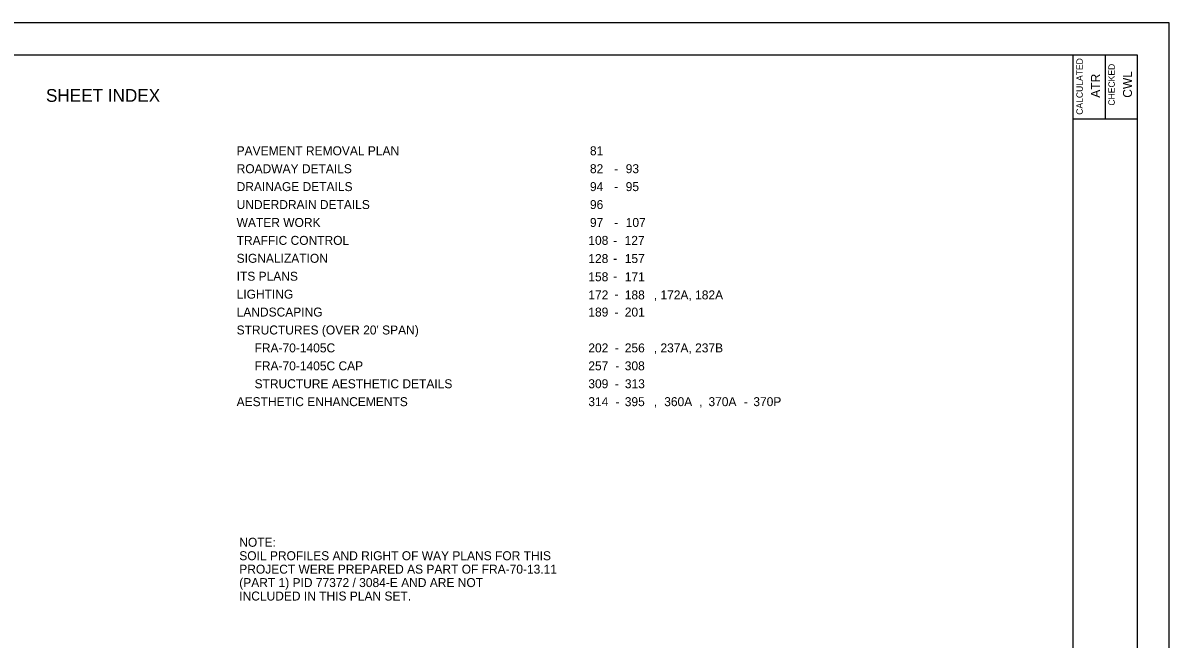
# Model space of a CAD drawing. Extents: x -42.2 to 34, y 0 to 22.
# Drawn here: x 16.1 to 34, y 12.37 to 22 of the extents above; entities that cross this region are included whole.
import ezdxf

# ---------------------------------------------------------------- set-up
doc = ezdxf.new("R2010")
doc.units = 0
for name, color, linetype in [('SH_Border', 7, 'Continuous'), ('SH_Cut_Line', 7, 'Continuous'), ('SH_Data', 7, 'Continuous')]:
    doc.layers.add(name, color=color, linetype=linetype)

msp = doc.modelspace()

# ---------------------------------------------------------------- linework, layer by layer
at = {"layer": 'SH_Border'}
for p, q in [((32.5, 0.5), (32.5, 21.5)), ((33, 21.5), (33, 20.5)), ((32.5, 20.5), (33.5, 20.5))]:
    msp.add_line(p, q, dxfattribs=at)
msp.add_lwpolyline([(2, 21.5), (33.5, 21.5), (33.5, 0.5), (2, 0.5)], close=True, dxfattribs=at)
at = {"layer": 'SH_Cut_Line'}
msp.add_lwpolyline([(0, 0), (34, 0), (34, 22), (0, 22)], close=True, dxfattribs=at)

# ---------------------------------------------------------------- texts
at = {"layer": 'SH_Data'}
for s, height, p in [('CALCULATED', 0.1, (32.652, 20.565)), ('CHECKED', 0.1, (33.152, 20.708)), ('ATR ', 0.14, (32.92, 20.831)), ('CWL ', 0.14, (33.42, 20.831))]:
    msp.add_text(s, height=height, rotation=90, dxfattribs=at).set_placement(p)
for s, height, p in [('SHEET INDEX ', 0.2, (16.459, 20.767)), ('PAVEMENT REMOVAL PLAN', 0.14, (19.437, 19.932)), ('81', 0.14, (24.955, 19.932)), ('ROADWAY DETAILS', 0.14, (19.437, 19.652)), ('82', 0.14, (24.955, 19.652)), ('-', 0.14, (25.333, 19.652)), ('93', 0.14, (25.514, 19.652)), ('DRAINAGE DETAILS', 0.14, (19.437, 19.372)), ('94', 0.14, (24.955, 19.372)), ('95', 0.14, (25.514, 19.372)), ('-', 0.14, (25.333, 19.372)), ('UNDERDRAIN DETAILS', 0.14, (19.437, 19.092)), ('96', 0.14, (24.955, 19.092)), ('WATER WORK', 0.14, (19.437, 18.812)), ('97', 0.14, (24.955, 18.812)), ('-', 0.14, (25.333, 18.812)), ('107', 0.14, (25.514, 18.812)), ('TRAFFIC CONTROL ', 0.14, (19.437, 18.532)), ('108', 0.14, (24.93, 18.532)), ('127', 0.14, (25.497, 18.532)), ('-', 0.14, (25.318, 18.532)), ('SIGNALIZATION', 0.14, (19.437, 18.252)), ('128', 0.14, (24.93, 18.248)), ('-', 0.14, (25.318, 18.252)), ('157', 0.14, (25.499, 18.248)), ('ITS PLANS', 0.14, (19.437, 17.972)), ('158', 0.14, (24.93, 17.964)), ('171', 0.14, (25.499, 17.964)), ('-', 0.14, (25.318, 17.972)), ('LIGHTING', 0.14, (19.437, 17.692)), ('172', 0.14, (24.93, 17.68)), ('-', 0.14, (25.339, 17.692)), ('188', 0.14, (25.499, 17.68)), (', 172A, 182A', 0.14, (25.952, 17.68)), ('LANDSCAPING', 0.14, (19.437, 17.412)), ('189', 0.14, (24.93, 17.412)), ('201', 0.14, (25.499, 17.412)), ('-', 0.14, (25.338, 17.412)), ("STRUCTURES (OVER 20' SPAN)", 0.14, (19.437, 17.132)), ('FRA-70-1405C', 0.14, (19.717, 16.852)), ('202', 0.14, (24.93, 16.852)), ('-', 0.14, (25.344, 16.852)), ('256', 0.14, (25.499, 16.852)), (', 237A, 237B', 0.14, (25.952, 16.852)), ('FRA-70-1405C CAP', 0.14, (19.717, 16.572)), ('257', 0.14, (24.93, 16.572)), ('308', 0.14, (25.499, 16.572)), ('-', 0.14, (25.352, 16.572)), ('STRUCTURE AESTHETIC DETAILS', 0.14, (19.717, 16.292)), ('309', 0.14, (24.93, 16.292)), ('-', 0.14, (25.345, 16.292)), ('313', 0.14, (25.5, 16.292)), ('AESTHETIC ENHANCEMENTS', 0.14, (19.437, 16.012)), ('314', 0.14, (24.93, 16.012)), ('395', 0.14, (25.499, 16.012)), ('360A', 0.14, (26.115, 16.012)), ('370A', 0.14, (26.806, 16.012)), ('370P', 0.14, (27.507, 16.012)), ('-', 0.14, (25.356, 16.012)), (',', 0.14, (25.952, 16.012)), (',', 0.14, (26.66, 16.012)), ('-', 0.14, (27.36, 16.012)), ('NOTE:', 0.14, (19.478, 13.815)), ('SOIL PROFILES AND RIGHT OF WAY PLANS FOR THIS ', 0.14, (19.478, 13.605)), ('PROJECT WERE PREPARED AS PART OF FRA-70-13.11 ', 0.14, (19.478, 13.395)), ('(PART 1) PID 77372 / 3084-E AND ARE NOT ', 0.14, (19.478, 13.185)), ('INCLUDED IN THIS PLAN SET.', 0.14, (19.478, 12.975))]:
    msp.add_text(s, height=height, dxfattribs=at).set_placement(p)

doc.saveas('drawing.dxf')
